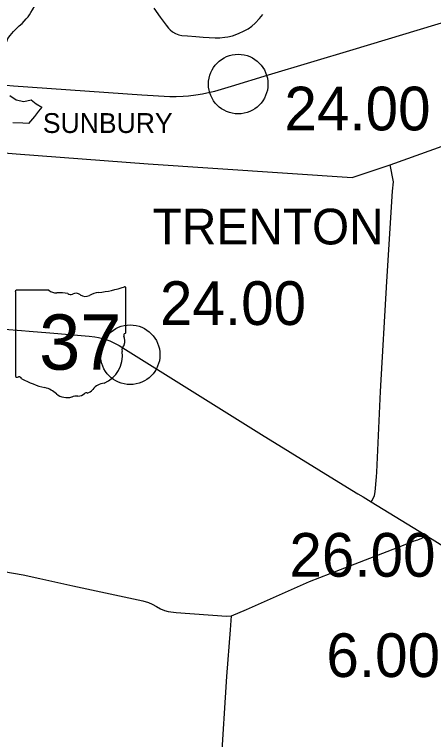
# Model space of a CAD drawing. Extents: x 1729596 to 1934326, y 644115 to 911751.
# Drawn here: x 1872161 to 1882714, y 803658 to 821917 of the extents above; entities that cross this region are included whole.
import ezdxf

# ---------------------------------------------------------------- set-up
doc = ezdxf.new("R2010")
doc.units = 0
for name, color, linetype in [('Default', 7, 'Continuous'), ('GM_X_Corporation', 7, 'Continuous'), ('GM_X_Corporation_Text', 7, 'Continuous'), ('GM_X_County_Road', 7, 'Continuous'), ('GM_X_State_Route', 7, 'Continuous'), ('GM_X_State_Shield', 7, 'Continuous'), ('GM_X_Township_Road', 7, 'Continuous'), ('GM_X_Township_Text', 7, 'Continuous'), ('GM_X_US_Route', 7, 'Continuous')]:
    doc.layers.add(name, color=color, linetype=linetype)

msp = doc.modelspace()

# ---------------------------------------------------------------- linework, layer by layer
at = {"layer": 'Default'}
for centre in [(1877795, 820165), (1875074, 813348)]:
    msp.add_circle(centre, 750, dxfattribs=at)
at = {"layer": 'GM_X_Corporation'}
msp.add_lwpolyline([(1872043, 819876), (1872199, 819766), (1872392, 819723), (1872582, 819770), (1872706, 819663), (1872848, 819582), (1872764, 819484), (1872661, 819350), (1872513, 819172), (1872369, 819183), (1872118, 819190)], dxfattribs=at)
at = {"layer": 'GM_X_County_Road'}
for points in [[(1871742, 820151), (1871742, 820151), (1871754, 820333), (1871771, 820532), (1871780, 820600), (1871796, 820672), (1871893, 821017), (1871942, 821170), (1871996, 821311), (1872051, 821390), (1872132, 821486), (1872206, 821558), (1872281, 821630), (1872352, 821694), (1872457, 821804), (1872502, 821861), (1872537, 821910), (1872571, 821965), (1872610, 822031), (1872673, 822132), (1872724, 822198)], [(1875667, 822073), (1875831, 821849), (1875981, 821648), (1876039, 821575), (1876079, 821533), (1876143, 821482), (1876217, 821438), (1876297, 821406), (1876374, 821389), (1876519, 821376), (1876727, 821364), (1876913, 821349), (1877214, 821328), (1877336, 821330), (1877454, 821342), (1877534, 821356), (1877649, 821382), (1877722, 821406), (1877821, 821445), (1877928, 821496), (1878043, 821558), (1878138, 821626), (1878219, 821701), (1878331, 821818), (1878413, 821920)], [(1871277, 818480), (1872206, 818406), (1875525, 818156), (1880663, 817814), (1881619, 818131), (1884362, 819111), (1887858, 818871), (1889457, 818761), (1891623, 818604), (1892346, 818560), (1895326, 818344), (1897532, 818224), (1897769, 818211), (1897801, 818204), (1897822, 818179)], [(1870615, 808110), (1872380, 807804), (1872796, 807716), (1873633, 807525), (1875394, 807147), (1875535, 807109), (1875625, 807069), (1875741, 807006), (1875837, 806950), (1875938, 806910), (1876028, 806878), (1876232, 806859), (1877504, 806767), (1877627, 806773), (1878001, 806934), (1879588, 807637), (1880629, 808038), (1881916, 808534), (1882228, 808657), (1882321, 808690), (1882416, 808728), (1882452, 808749), (1882473, 808770), (1882507, 808811)], [(1877369, 802994), (1877508, 805242), (1877600, 806419), (1877627, 806773)]]:
    msp.add_lwpolyline(points, dxfattribs=at)
at = {"layer": 'GM_X_State_Route'}
msp.add_lwpolyline([(1871455, 814026), (1871491, 814021), (1871569, 814014), (1871759, 814000), (1871910, 813989), (1872340, 813955), (1872527, 813939), (1873053, 813896), (1874044, 813812), (1874182, 813797), (1874274, 813782), (1874381, 813759), (1874562, 813699), (1874700, 813634), (1874793, 813581), (1874892, 813523), (1878383, 811338), (1880549, 810005), (1880810, 809846), (1880939, 809769), (1881144, 809643), (1882507, 808811), (1883124, 808426)], dxfattribs=at)
at = {"layer": 'GM_X_State_Shield'}
for p, q in [((1872182, 814935), (1872182, 812822)), ((1872182, 814935), (1872182, 812822)), ((1873024, 814972), (1872209, 814972)), ((1873024, 814972), (1872209, 814972)), ((1874966, 813919), (1874966, 815024)), ((1874966, 813919), (1874966, 815024)), ((1874966, 813919), (1874966, 813919)), ((1874966, 813919), (1874966, 813919))]:
    msp.add_line(p, q, dxfattribs=at)
for centre, radius, start, end in [((1872213, 814940), 32.3, 98.1301, 188.1301), ((1872213, 814940), 32.3, 98.1301, 188.1301), ((1873219, 815217), 313, 231.6195, 271.1119), ((1873219, 815217), 313, 231.6195, 271.1119), ((1873322, 813785), 1123, 80.4867, 94.9883), ((1873322, 813785), 1123, 80.4867, 94.9883), ((1874351, 814326), 594, 97.3462, 120.7689), ((1874351, 814326), 594, 97.3462, 120.7689), ((1873974, 817853), 2953, 275.8445, 288.9065), ((1873974, 817853), 2953, 275.8445, 288.9065), ((1874935, 815029), 31, 351.8621, 97.738), ((1874935, 815029), 31, 351.8621, 97.738), ((1873577, 814951), 90.3, 219.7921, 297.1024), ((1873577, 814951), 90.3, 219.7921, 297.1024), ((1873710, 814707), 188, 54.4667, 119.1411), ((1873710, 814707), 188, 54.4667, 119.1411), ((1873952, 815042), 226, 233.8562, 294.8282), ((1873952, 815042), 226, 233.8562, 294.8282), ((1874959, 813838), 48, 107.944, 210.337), ((1874959, 813838), 48, 107.944, 210.337), ((1874654, 813698), 288, 340.033, 23.6496), ((1874654, 813698), 288, 340.033, 23.6496), ((1874933, 813914), 33.2, 289.6038, 7.7341), ((1874933, 813914), 33.2, 289.6038, 7.7341), ((1875077, 813456), 210, 136.8065, 186.9296), ((1875077, 813456), 210, 136.8065, 186.9296), ((1874139, 813315), 739, 292.3089, 8.9858), ((1874139, 813315), 739, 292.3089, 8.9858), ((1872214, 812818), 32.5, 171.9584, 258.3066), ((1872214, 812818), 32.5, 171.9584, 258.3066), ((1872219, 813034), 248, 267.339, 280.6039), ((1872219, 813034), 248, 267.339, 280.6039), ((1872269, 812700), 89.5, 29.7484, 93.2717), ((1872269, 812700), 89.5, 29.7484, 93.2717), ((1873400, 814599), 2132, 240.4129, 257.1985), ((1873400, 814599), 2132, 240.4129, 257.1985), ((1874451, 812229), 404, 94.4031, 142.5768), ((1874451, 812229), 404, 94.4031, 142.5768), ((1872764, 811873), 667, 47.1842, 75.836), ((1872764, 811873), 667, 47.1842, 75.836), ((1873486, 812690), 423, 230.7004, 286.2918), ((1873486, 812690), 423, 230.7004, 286.2918), ((1873761, 812531), 226, 268.777, 315.5493), ((1873761, 812531), 226, 268.777, 315.5493), ((1873965, 812327), 63.5, 65.7517, 132.6484), ((1873965, 812327), 63.5, 65.7517, 132.6484), ((1873938, 812617), 239, 282.8732, 323.2771), ((1873938, 812617), 239, 282.8732, 323.2771), ((1873731, 811959), 348, 85.6951, 111.2099), ((1873731, 811959), 348, 85.6951, 111.2099)]:
    msp.add_arc(centre, radius, start, end, dxfattribs=at)
at = {"layer": 'GM_X_Township_Road'}
msp.add_lwpolyline([(1881144, 809643), (1881165, 809679), (1881231, 809806), (1881247, 809894), (1881278, 810269), (1881288, 810392), (1881379, 812426), (1881535, 815194), (1881680, 817467), (1881704, 817701), (1881619, 818131)], dxfattribs=at)
at = {"layer": 'GM_X_US_Route'}
msp.add_lwpolyline([(1871153, 820180), (1871199, 820179), (1871742, 820151), (1872137, 820124), (1875367, 819897), (1876072, 819853), (1876232, 819852), (1876406, 819857), (1876545, 819867), (1876727, 819890), (1876899, 819917), (1877009, 819941), (1877209, 819989), (1877624, 820113), (1878554, 820394), (1880687, 821035), (1883192, 821790)], dxfattribs=at)

# ---------------------------------------------------------------- texts
at = {"layer": 'Default'}
for s, p in [('24.00', (1878959, 818999)), ('24.00', (1875824, 814098)), ('26.00', (1879084, 807758)), ('6.00', (1880016, 805231))]:
    msp.add_text(s, height=1100, dxfattribs=at).set_placement(p)
at = {"layer": 'GM_X_Corporation_Text'}
msp.add_text('SUNBURY', height=500, rotation=0, dxfattribs=at).set_placement((1872874, 818933))
at = {"layer": 'GM_X_State_Shield'}
msp.add_text('37', height=1392.2, dxfattribs=at).set_placement((1872782, 812971))
msp.add_text('37', height=1392.2, dxfattribs=at).set_placement((1872782, 812971))
at = {"layer": 'GM_X_Township_Text'}
msp.add_text('TRENTON', height=900, rotation=0, dxfattribs=at).set_placement((1875642, 816126))

doc.saveas('drawing.dxf')
